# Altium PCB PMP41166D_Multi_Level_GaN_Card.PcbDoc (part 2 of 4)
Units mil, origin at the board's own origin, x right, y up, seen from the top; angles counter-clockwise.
Board outline 3221.72 x 1840 mil, 6 copper layers (Top Layer, Signal Layer 1, Signal Layer 2, Signal Layer 3, Signal Layer 4, Bottom Layer), stack 51.8 mil thick; 155 components, 123 nets, 580 pads, 278 vias.
Unrouted connection lines stored in the file: 2.
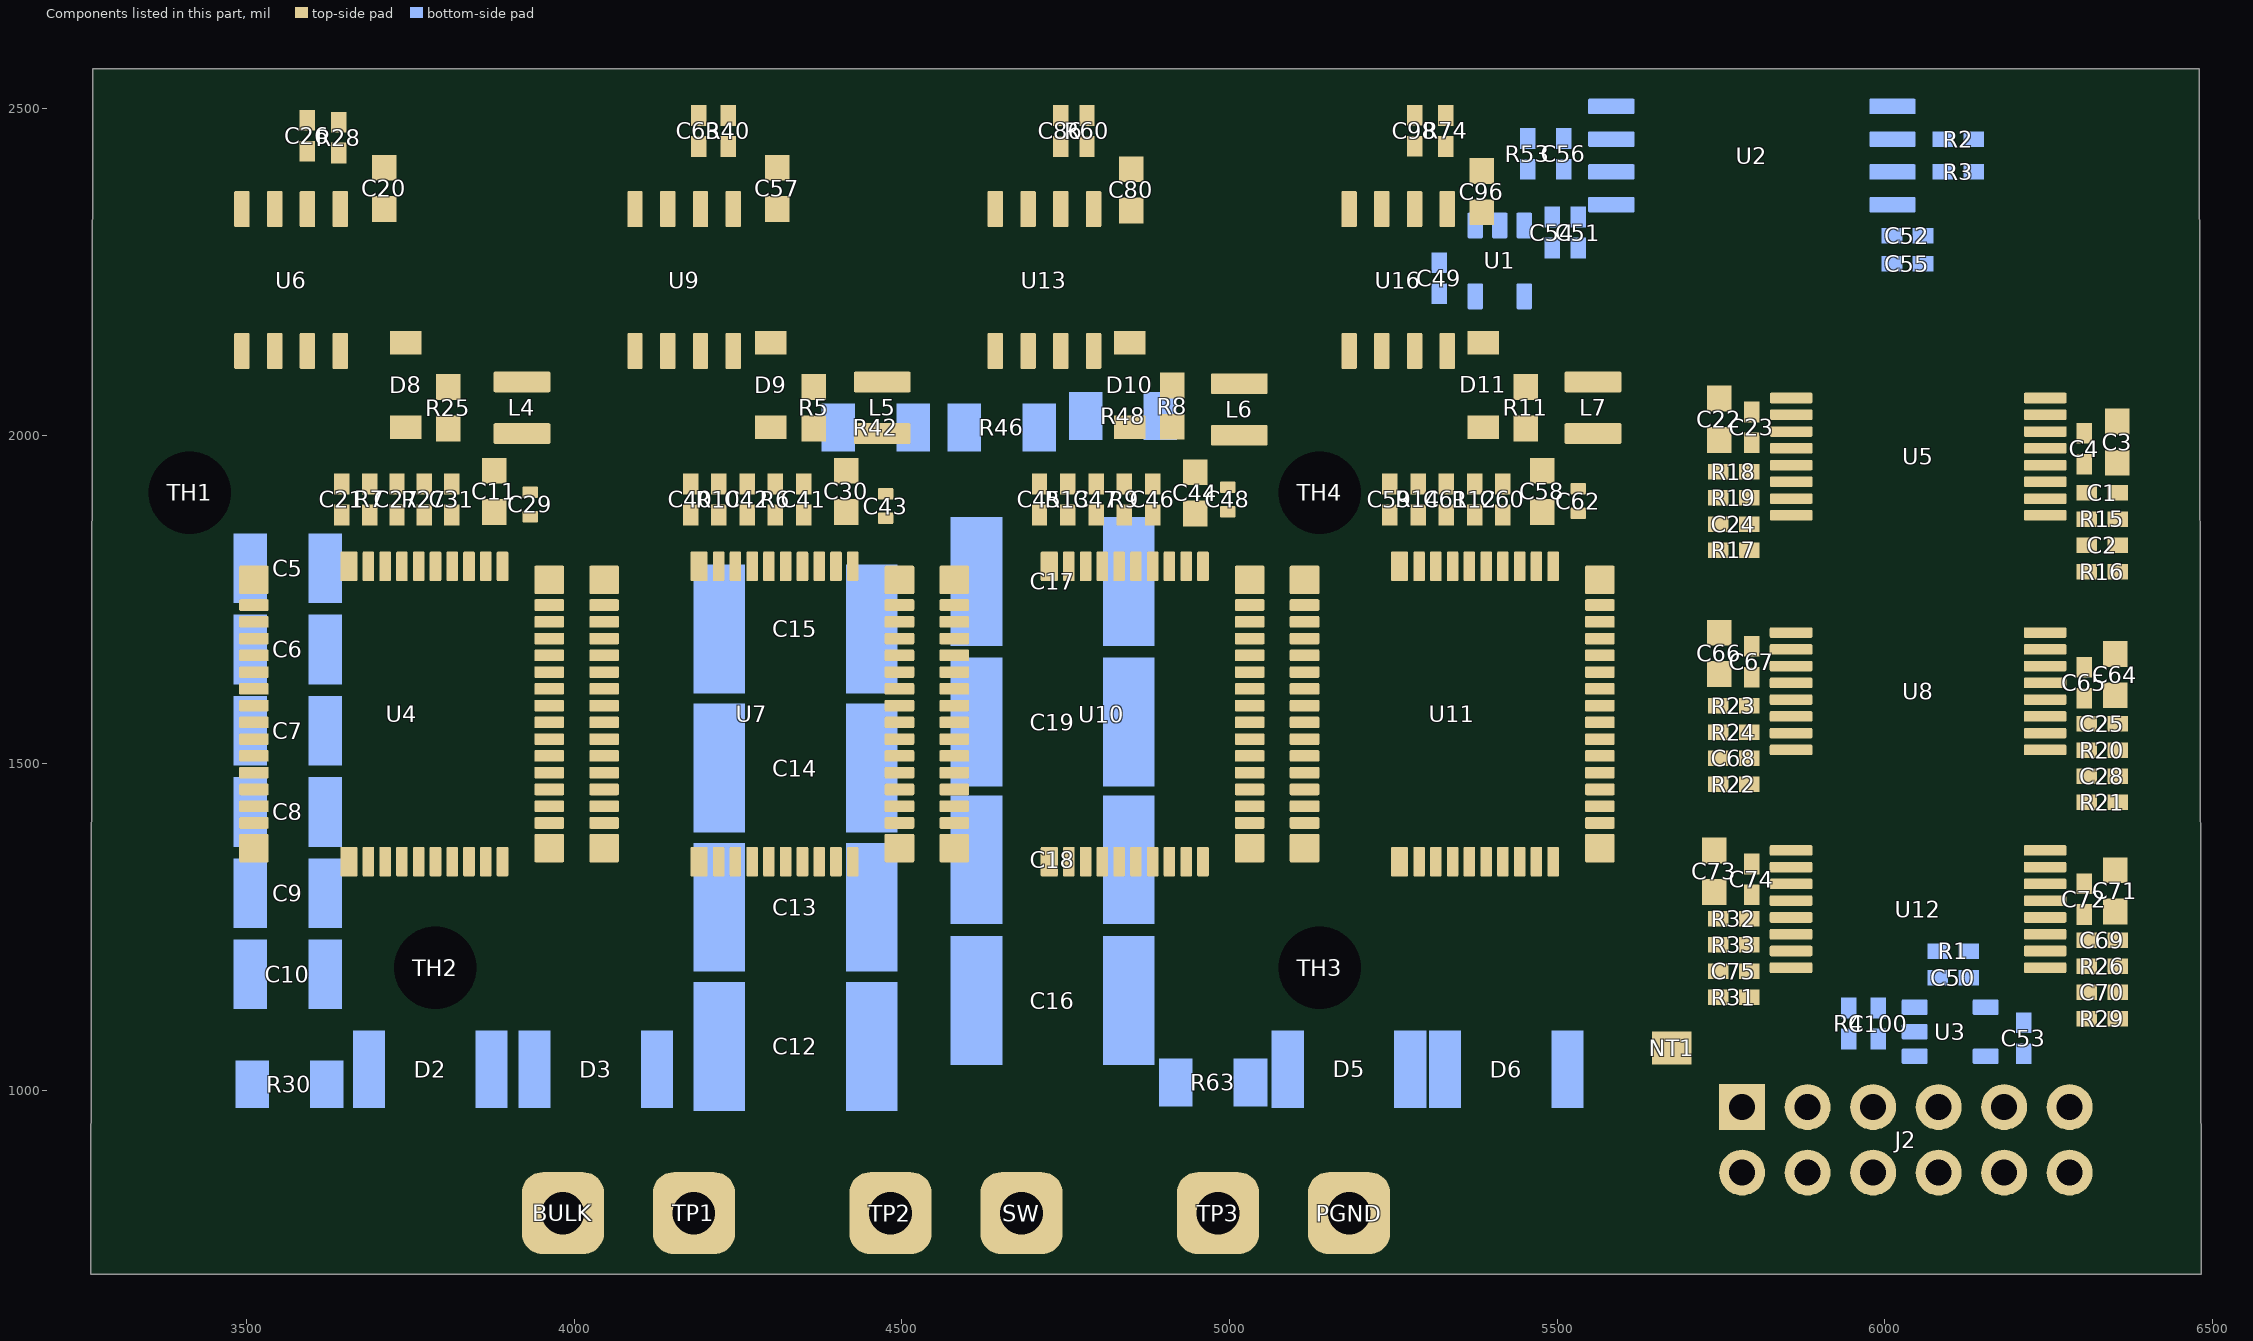
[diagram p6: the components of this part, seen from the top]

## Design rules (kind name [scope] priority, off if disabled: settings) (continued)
PolygonConnect PolygonConnect_38 [All vs IsNamedPolygon('SWNODE') Or  IsNamedPolygon('D403_2') Or  IsNamedPolygon('D403_2') Or  IsNamedPolygon('PGND') Or  IsNamedPolygon('BOTTOM_LAYER_NETC106_2_P030') Or  IsNamedPolygon('C102_1') Or  IsNamedPolygon('SGND') Or  IsNamedPolygon('TOP_LAYER_54V1_P046') Or  IsNamedPolygon('TOP_LAYER_54V2_P048') Or  IsNamedPolygon('TOP_LAYER_54V2_P048') Or  IsNamedPolygon('C108_1') Or  IsNamedPolygon('C108_1') Or  IsNamedPolygon('C108_1') Or  IsNamedPolygon('C108_1') Or  IsNamedPolygon('C108_1') Or  IsNamedPolygon('C108_1') Or  IsNamedPolygon('PGND') Or  IsNamedPolygon('ZCD') Or  IsNamedPolygon('Line') Or  IsNamedPolygon('5Vp') Or  IsNamedPolygon('12Vp') Or  IsNamedPolygon('T200_4') Or  IsNamedPolygon('T200_6') Or  IsNamedPolygon('SWNODE3') Or  IsNamedPolygon('T200_4') Or  IsNamedPolygon('T200_6') Or  IsNamedPolygon('SWNODE4') Or  IsNamedPolygon('VSR') Or  IsNamedPolygon('Iout_SNS') Or  IsNamedPolygon('SIGNAL_LAYER_2_VBB_P094') Or  IsNamedPolygon('Vbulk1') Or  IsNamedPolygon('VBB') Or  IsNamedPolygon('SIGNAL_LAYER_1_VBULK1_P106') Or  IsNamedPolygon('Line') Or  IsNamedPolygon('Line') Or  IsNamedPolygon('Line') Or  IsNamedPolygon('D404_2') Or  IsNamedPolygon('VBB') Or  IsNamedPolygon('D400_2') Or  IsNamedPolygon('SGND') Or  IsNamedPolygon('PGND') Or  IsNamedPolygon('TOP_LAYER_12VS_P126') Or  IsNamedPolygon('BOTTOM_LAYER_54V1_P128') Or  IsNamedPolygon('LEG3_HS_DRV') Or  IsNamedPolygon('LEG4_LS_DRV') Or  IsNamedPolygon('LEG4_HS_DRV') Or  IsNamedPolygon('SWNODE4') Or  IsNamedPolygon('SWNODE3') Or  IsNamedPolygon('T200_6') Or  IsNamedPolygon('T200_4') Or  IsNamedPolygon('VBB') Or  IsNamedPolygon('5Vs') Or  IsNamedPolygon('SGND') Or  IsNamedPolygon('Iout_SNS') Or  IsNamedPolygon('SGND') Or  IsNamedPolygon('SWNODE3') Or  IsNamedPolygon('SWNODE3') Or  IsNamedPolygon('SWNODE3') Or  IsNamedPolygon('SWNODE3') Or  IsNamedPolygon('SGND') Or  IsNamedPolygon('SGND') Or  IsNamedPolygon('SGND') Or  IsNamedPolygon('SWNODE4') Or  IsNamedPolygon('SWNODE4') Or  IsNamedPolygon('SWNODE4') Or  IsNamedPolygon('VSR') Or  IsNamedPolygon('SWNODE3') Or  IsNamedPolygon('SGND') Or  IsNamedPolygon('SGND') Or  IsNamedPolygon('SGND') Or  IsNamedPolygon('SGND') Or  IsNamedPolygon('SGND') Or  IsNamedPolygon('SGND') Or  IsNamedPolygon('BOTTOM_LAYER_54V1_P128') Or  IsNamedPolygon('SGND') Or  IsNamedPolygon('VSR') Or  IsNamedPolygon('C102_1') Or  IsNamedPolygon('C102_1') Or  IsNamedPolygon('C102_1') Or  IsNamedPolygon('C102_1') Or  IsNamedPolygon('C102_1') Or  IsNamedPolygon('ZCD') Or  IsNamedPolygon('PGND') Or  IsNamedPolygon('PGND') Or  IsNamedPolygon('Vbulk1') Or  IsNamedPolygon('VBB') Or  IsNamedPolygon('Vbulk1') Or  IsNamedPolygon('Vbulk1') Or  IsNamedPolygon('ZCD') Or  IsNamedPolygon('Neutral') Or  IsNamedPolygon('Neutral')] p22: connectstyle=Direct reliefconductorwidth=10 reliefentries=4 polygonreliefangle="90 Angle" airgapwidth=10
PolygonConnect PolygonConnect_37 [All vs IsNamedPolygon('SGND') Or  IsNamedPolygon('SWNODE4') Or  IsNamedPolygon('5Vp') Or  IsNamedPolygon('SWNODE4') Or  IsNamedPolygon('VBB') Or  IsNamedPolygon('Line') Or  IsNamedPolygon('SGND') Or  IsNamedPolygon('SIGNAL_LAYER_2_C102_1_P032') Or  IsNamedPolygon('TOP_LAYER_54V2_P048') Or  IsNamedPolygon('ZCD') Or  IsNamedPolygon('PGND') Or  IsNamedPolygon('SIGNAL_LAYER_2_VBB_P094') Or  IsNamedPolygon('Line') Or  IsNamedPolygon('Line') Or  IsNamedPolygon('D404_2') Or  IsNamedPolygon('PGND') Or  IsNamedPolygon('SIGNAL_LAYER_1_ZCD_P108') Or  IsNamedPolygon('SWNODE3') Or  IsNamedPolygon('SIGNAL_LAYER_4_C102_1_P038') Or  IsNamedPolygon('SWNODE3') Or  IsNamedPolygon('LEG4_HS_DRV') Or  IsNamedPolygon('SWNODE4') Or  IsNamedPolygon('5Vs') Or  IsNamedPolygon('VBB') Or  IsNamedPolygon('TOP_LAYER_54V2_P048') Or  IsNamedPolygon('C102_1') Or  IsNamedPolygon('LEG4_LS_DRV') Or  IsNamedPolygon('T200_4') Or  IsNamedPolygon('SWNODE3') Or  IsNamedPolygon('Line') Or  IsNamedPolygon('SGND') Or  IsNamedPolygon('SGND') Or  IsNamedPolygon('SWNODE4') Or  IsNamedPolygon('12Vp') Or  IsNamedPolygon('BOTTOM_LAYER_NETC106_2_P030') Or  IsNamedPolygon('T200_4') Or  IsNamedPolygon('Vbulk1') Or  IsNamedPolygon('C108_1') Or  IsNamedPolygon('BOTTOM_LAYER_54V1_P128') Or  IsNamedPolygon('BOTTOM_LAYER_54V1_P128') Or  IsNamedPolygon('SWNODE') Or  IsNamedPolygon('Iout_SNS') Or  IsNamedPolygon('VSR') Or  IsNamedPolygon('D400_2') Or  IsNamedPolygon('D403_2') Or  IsNamedPolygon('SWNODE3') Or  IsNamedPolygon('T200_6') Or  IsNamedPolygon('SWNODE3') Or  IsNamedPolygon('C108_1') Or  IsNamedPolygon('PGND') Or  IsNamedPolygon('BOTTOM_LAYER_VBULK1_P096') Or  IsNamedPolygon('BOTTOM_LAYER_54V1_P128') Or  IsNamedPolygon('TOP_LAYER_12VS_P126') Or  IsNamedPolygon('SIGNAL_LAYER_1_VBULK1_P106') Or  IsNamedPolygon('T200_4') Or  IsNamedPolygon('SGND') Or  IsNamedPolygon('C108_1') Or  IsNamedPolygon('SWNODE3') Or  IsNamedPolygon('T200_6') Or  IsNamedPolygon('T200_6') Or  IsNamedPolygon('T200_6') Or  IsNamedPolygon('SGND') Or  IsNamedPolygon('C108_1') Or  IsNamedPolygon('SGND') Or  IsNamedPolygon('VBB') Or  IsNamedPolygon('T200_4') Or  IsNamedPolygon('LEG3_HS_DRV') Or  IsNamedPolygon('C108_1') Or  IsNamedPolygon('D403_2') Or  IsNamedPolygon('Iout_SNS') Or  IsNamedPolygon('C108_1') Or  IsNamedPolygon('SWNODE4')] p23: connectstyle=Direct reliefconductorwidth=10 reliefentries=4 polygonreliefangle="90 Angle" airgapwidth=10
PolygonConnect PolygonConnect_36 [All vs IsNamedPolygon('PGND') Or  IsNamedPolygon('BOTTOM_LAYER_54V1_P128') Or  IsNamedPolygon('SGND') Or  IsNamedPolygon('LEG4_LS_DRV') Or  IsNamedPolygon('TOP_LAYER_12VS_P126') Or  IsNamedPolygon('LEG4_HS_DRV') Or  IsNamedPolygon('LEG3_HS_DRV') Or  IsNamedPolygon('SGND') Or  IsNamedPolygon('C108_1') Or  IsNamedPolygon('12Vp') Or  IsNamedPolygon('D403_2') Or  IsNamedPolygon('SIGNAL_LAYER_1_ZCD_P108') Or  IsNamedPolygon('C108_1') Or  IsNamedPolygon('BOTTOM_LAYER_VBULK1_P096') Or  IsNamedPolygon('SWNODE') Or  IsNamedPolygon('T200_4') Or  IsNamedPolygon('D400_2') Or  IsNamedPolygon('C102_1') Or  IsNamedPolygon('Line') Or  IsNamedPolygon('VBB') Or  IsNamedPolygon('Line') Or  IsNamedPolygon('TOP_LAYER_54V2_P048') Or  IsNamedPolygon('BOTTOM_LAYER_NETC106_2_P030') Or  IsNamedPolygon('SIGNAL_LAYER_1_VBULK1_P106') Or  IsNamedPolygon('Line') Or  IsNamedPolygon('5Vp') Or  IsNamedPolygon('BOTTOM_LAYER_54V1_P128') Or  IsNamedPolygon('D404_2') Or  IsNamedPolygon('C108_1') Or  IsNamedPolygon('VSR') Or  IsNamedPolygon('T200_6') Or  IsNamedPolygon('VBB') Or  IsNamedPolygon('C108_1') Or  IsNamedPolygon('SIGNAL_LAYER_2_C102_1_P032') Or  IsNamedPolygon('SGND') Or  IsNamedPolygon('PGND') Or  IsNamedPolygon('SIGNAL_LAYER_4_C102_1_P038') Or  IsNamedPolygon('Vbulk1') Or  IsNamedPolygon('TOP_LAYER_54V2_P048') Or  IsNamedPolygon('Iout_SNS') Or  IsNamedPolygon('PGND') Or  IsNamedPolygon('T200_4') Or  IsNamedPolygon('ZCD') Or  IsNamedPolygon('Line') Or  IsNamedPolygon('C108_1') Or  IsNamedPolygon('D403_2') Or  IsNamedPolygon('SIGNAL_LAYER_2_VBB_P094') Or  IsNamedPolygon('SGND') Or  IsNamedPolygon('C108_1') Or  IsNamedPolygon('SIGNAL_LAYER_1_IOUT_SNS_P044') Or  IsNamedPolygon('BOTTOM_LAYER_54V1_P128') Or  IsNamedPolygon('T200_6')] p24: connectstyle=Direct reliefconductorwidth=10 reliefentries=4 polygonreliefangle="90 Angle" airgapwidth=10
PolygonConnect PolygonConnect_35 [All vs IsNamedPolygon('SWNODE') Or  IsNamedPolygon('D403_2') Or  IsNamedPolygon('D403_2') Or  IsNamedPolygon('PGND') Or  IsNamedPolygon('BOTTOM_LAYER_NETC106_2_P030') Or  IsNamedPolygon('SIGNAL_LAYER_2_C102_1_P032') Or  IsNamedPolygon('C102_1') Or  IsNamedPolygon('SIGNAL_LAYER_4_C102_1_P038') Or  IsNamedPolygon('SGND') Or  IsNamedPolygon('SIGNAL_LAYER_1_IOUT_SNS_P044') Or  IsNamedPolygon('BOTTOM_LAYER_54V1_P128') Or  IsNamedPolygon('TOP_LAYER_54V2_P048') Or  IsNamedPolygon('BOTTOM_LAYER_54V1_P128') Or  IsNamedPolygon('TOP_LAYER_54V2_P048') Or  IsNamedPolygon('C108_1') Or  IsNamedPolygon('C108_1') Or  IsNamedPolygon('C108_1') Or  IsNamedPolygon('C108_1') Or  IsNamedPolygon('C108_1') Or  IsNamedPolygon('C108_1') Or  IsNamedPolygon('PGND') Or  IsNamedPolygon('ZCD') Or  IsNamedPolygon('Line') Or  IsNamedPolygon('5Vp') Or  IsNamedPolygon('12Vp') Or  IsNamedPolygon('T200_4') Or  IsNamedPolygon('T200_6') Or  IsNamedPolygon('SGND') Or  IsNamedPolygon('T200_4') Or  IsNamedPolygon('T200_6') Or  IsNamedPolygon('SGND') Or  IsNamedPolygon('VSR') Or  IsNamedPolygon('Iout_SNS') Or  IsNamedPolygon('SIGNAL_LAYER_2_VBB_P094') Or  IsNamedPolygon('BOTTOM_LAYER_VBULK1_P096') Or  IsNamedPolygon('Vbulk1') Or  IsNamedPolygon('VBB') Or  IsNamedPolygon('SIGNAL_LAYER_1_VBULK1_P106') Or  IsNamedPolygon('SIGNAL_LAYER_1_ZCD_P108') Or  IsNamedPolygon('Line') Or  IsNamedPolygon('Line') Or  IsNamedPolygon('Line') Or  IsNamedPolygon('D404_2') Or  IsNamedPolygon('VBB') Or  IsNamedPolygon('D400_2') Or  IsNamedPolygon('SGND') Or  IsNamedPolygon('PGND') Or  IsNamedPolygon('TOP_LAYER_12VS_P126') Or  IsNamedPolygon('BOTTOM_LAYER_54V1_P128') Or  IsNamedPolygon('LEG3_HS_DRV')] p25: connectstyle=Direct reliefconductorwidth=10 reliefentries=4 polygonreliefangle="90 Angle" airgapwidth=10
PolygonConnect PolygonConnect_34 [All vs IsNamedPolygon('SWNODE') Or  IsNamedPolygon('D403_2') Or  IsNamedPolygon('D403_2') Or  IsNamedPolygon('PGND') Or  IsNamedPolygon('BOTTOM_LAYER_NETC106_2_P030') Or  IsNamedPolygon('SIGNAL_LAYER_2_C102_1_P032') Or  IsNamedPolygon('C102_1') Or  IsNamedPolygon('SIGNAL_LAYER_4_C102_1_P038') Or  IsNamedPolygon('SGND') Or  IsNamedPolygon('SIGNAL_LAYER_1_IOUT_SNS_P044') Or  IsNamedPolygon('BOTTOM_LAYER_54V1_P128') Or  IsNamedPolygon('TOP_LAYER_54V2_P048') Or  IsNamedPolygon('BOTTOM_LAYER_54V1_P128') Or  IsNamedPolygon('TOP_LAYER_54V2_P048') Or  IsNamedPolygon('C108_1') Or  IsNamedPolygon('C108_1') Or  IsNamedPolygon('C108_1') Or  IsNamedPolygon('C108_1') Or  IsNamedPolygon('C108_1') Or  IsNamedPolygon('C108_1') Or  IsNamedPolygon('PGND') Or  IsNamedPolygon('ZCD') Or  IsNamedPolygon('Line') Or  IsNamedPolygon('5Vp') Or  IsNamedPolygon('12Vp') Or  IsNamedPolygon('T200_4') Or  IsNamedPolygon('T200_6') Or  IsNamedPolygon('SGND') Or  IsNamedPolygon('T200_4') Or  IsNamedPolygon('T200_6') Or  IsNamedPolygon('SGND') Or  IsNamedPolygon('VSR') Or  IsNamedPolygon('Iout_SNS') Or  IsNamedPolygon('SIGNAL_LAYER_2_VBB_P094') Or  IsNamedPolygon('BOTTOM_LAYER_VBULK1_P096') Or  IsNamedPolygon('Vbulk1') Or  IsNamedPolygon('VBB') Or  IsNamedPolygon('SIGNAL_LAYER_1_VBULK1_P106') Or  IsNamedPolygon('SIGNAL_LAYER_1_ZCD_P108') Or  IsNamedPolygon('Line') Or  IsNamedPolygon('Line') Or  IsNamedPolygon('Line') Or  IsNamedPolygon('D404_2') Or  IsNamedPolygon('VBB') Or  IsNamedPolygon('D400_2') Or  IsNamedPolygon('SGND')] p26: connectstyle=Direct reliefconductorwidth=10 reliefentries=4 polygonreliefangle="90 Angle" airgapwidth=10
PolygonConnect PolygonConnect_33 [All vs IsNamedPolygon('SIGNAL_LAYER_1_VBULK1_P106')] p27: connectstyle=Direct reliefconductorwidth=10 reliefentries=4 polygonreliefangle="90 Angle" airgapwidth=10
PolygonConnect PolygonConnect_32 [All vs IsNamedPolygon('SIGNAL_LAYER_1_VBULK1_P106')] p28: connectstyle=Direct reliefconductorwidth=10 reliefentries=4 polygonreliefangle="90 Angle" airgapwidth=10
PolygonConnect PolygonConnect_31 [All vs IsNamedPolygon('SIGNAL_LAYER_1_VBULK1_P106')] p29: connectstyle=Direct reliefconductorwidth=10 reliefentries=4 polygonreliefangle="90 Angle" airgapwidth=10
PolygonConnect PolygonConnect_30 [All vs IsNamedPolygon('VBB')] p30: connectstyle=Direct reliefconductorwidth=10 reliefentries=4 polygonreliefangle="90 Angle" airgapwidth=10
PolygonConnect PolygonConnect_29 [All vs IsNamedPolygon('SGND')] p31: connectstyle=Direct reliefconductorwidth=10 reliefentries=4 polygonreliefangle="90 Angle" airgapwidth=10
PolygonConnect PolygonConnect_28 [All vs IsNamedPolygon('Vbulk1')] p32: connectstyle=Direct reliefconductorwidth=10 reliefentries=4 polygonreliefangle="90 Angle" airgapwidth=10
PolygonConnect PolygonConnect_27 [All vs IsNamedPolygon('BOTTOM_LAYER_VBULK1_P096')] p33: connectstyle=Direct reliefconductorwidth=10 reliefentries=4 polygonreliefangle="90 Angle" airgapwidth=10
PolygonConnect PolygonConnect_26 [All vs IsNamedPolygon('SIGNAL_LAYER_2_VBB_P094')] p34: connectstyle=Direct reliefconductorwidth=10 reliefentries=4 polygonreliefangle="90 Angle" airgapwidth=10
PolygonConnect PolygonConnect_25 [All vs IsNamedPolygon('C108_1')] p35: connectstyle=Direct reliefconductorwidth=10 reliefentries=4 polygonreliefangle="90 Angle" airgapwidth=10
PolygonConnect PolygonConnect_24 [All vs IsNamedPolygon('BOTTOM_LAYER_EARTH_P100')] p36: connectstyle=Direct reliefconductorwidth=10 reliefentries=4 polygonreliefangle="90 Angle" airgapwidth=10
PolygonConnect PolygonConnect_23 [All vs IsNamedPolygon('BOTTOM_LAYER_54V1_P128')] p37: connectstyle=Direct reliefconductorwidth=10 reliefentries=4 polygonreliefangle="90 Angle" airgapwidth=10
PolygonConnect PolygonConnect_22 [All vs IsNamedPolygon('BOTTOM_LAYER_VBULK1_P096')] p38: connectstyle=Direct reliefconductorwidth=10 reliefentries=4 polygonreliefangle="90 Angle" airgapwidth=10
PolygonConnect PolygonConnect_21 [All vs IsNamedPolygon('SIGNAL_LAYER_2_VBB_P094')] p39: connectstyle=Direct reliefconductorwidth=10 reliefentries=4 polygonreliefangle="90 Angle" airgapwidth=10
PolygonConnect PolygonConnect_20 [All vs IsNamedPolygon('Iout_SNS')] p40: connectstyle=Direct reliefconductorwidth=10 reliefentries=4 polygonreliefangle="90 Angle" airgapwidth=10
PolygonConnect PolygonConnect_19 [All vs IsNamedPolygon('C108_1') Or  IsNamedPolygon('BOTTOM_LAYER_NETC106_2_P030') Or  IsNamedPolygon('D403_2') Or  IsNamedPolygon('C102_1') Or  IsNamedPolygon('SWNODE') Or  IsNamedPolygon('D403_2') Or  IsNamedPolygon('SIGNAL_LAYER_4_C102_1_P038') Or  IsNamedPolygon('PGND') Or  IsNamedPolygon('SIGNAL_LAYER_2_C102_1_P032') Or  IsNamedPolygon('SIGNAL_LAYER_1_IOUT_SNS_P044') Or  IsNamedPolygon('SGND') Or  IsNamedPolygon('C108_1') Or  IsNamedPolygon('BOTTOM_LAYER_54V1_P128') Or  IsNamedPolygon('C108_1') Or  IsNamedPolygon('C108_1') Or  IsNamedPolygon('TOP_LAYER_54V2_P048') Or  IsNamedPolygon('BOTTOM_LAYER_54V1_P128') Or  IsNamedPolygon('TOP_LAYER_54V2_P048') Or  IsNamedPolygon('C108_1') Or  IsNamedPolygon('C108_1') Or  IsNamedPolygon('12Vp') Or  IsNamedPolygon('5Vp') Or  IsNamedPolygon('Line') Or  IsNamedPolygon('T200_4') Or  IsNamedPolygon('SGND') Or  IsNamedPolygon('VSR') Or  IsNamedPolygon('ZCD') Or  IsNamedPolygon('PGND') Or  IsNamedPolygon('T200_6') Or  IsNamedPolygon('Neutral') Or  IsNamedPolygon('T200_4') Or  IsNamedPolygon('SGND') Or  IsNamedPolygon('T200_6')] p41: connectstyle=Direct reliefconductorwidth=10 reliefentries=4 polygonreliefangle="90 Angle" airgapwidth=10
PolygonConnect PolygonConnect_18 [All vs IsNamedPolygon('SWNODE') Or  IsNamedPolygon('D403_2') Or  IsNamedPolygon('D403_2') Or  IsNamedPolygon('PGND') Or  IsNamedPolygon('BOTTOM_LAYER_NETC106_2_P030') Or  IsNamedPolygon('SIGNAL_LAYER_2_C102_1_P032') Or  IsNamedPolygon('C102_1') Or  IsNamedPolygon('SIGNAL_LAYER_4_C102_1_P038') Or  IsNamedPolygon('SGND') Or  IsNamedPolygon('SIGNAL_LAYER_1_IOUT_SNS_P044') Or  IsNamedPolygon('BOTTOM_LAYER_54V1_P128') Or  IsNamedPolygon('TOP_LAYER_54V2_P048') Or  IsNamedPolygon('BOTTOM_LAYER_54V1_P128') Or  IsNamedPolygon('TOP_LAYER_54V2_P048') Or  IsNamedPolygon('C108_1') Or  IsNamedPolygon('C108_1') Or  IsNamedPolygon('C108_1') Or  IsNamedPolygon('C108_1') Or  IsNamedPolygon('C108_1') Or  IsNamedPolygon('C108_1') Or  IsNamedPolygon('Neutral') Or  IsNamedPolygon('PGND') Or  IsNamedPolygon('ZCD') Or  IsNamedPolygon('Line') Or  IsNamedPolygon('5Vp') Or  IsNamedPolygon('12Vp') Or  IsNamedPolygon('T200_4') Or  IsNamedPolygon('T200_6') Or  IsNamedPolygon('SGND') Or  IsNamedPolygon('T200_4') Or  IsNamedPolygon('T200_6') Or  IsNamedPolygon('SGND')] p42: connectstyle=Direct reliefconductorwidth=10 reliefentries=4 polygonreliefangle="90 Angle" airgapwidth=10
PolygonConnect PolygonConnect_17 [All vs IsNamedPolygon('12Vp') Or  IsNamedPolygon('T200_4') Or  IsNamedPolygon('T200_6') Or  IsNamedPolygon('SGND') Or  IsNamedPolygon('TOP_LAYER_54V2_P048') Or  IsNamedPolygon('SIGNAL_LAYER_1_IOUT_SNS_P044') Or  IsNamedPolygon('BOTTOM_LAYER_54V1_P128') Or  IsNamedPolygon('SGND') Or  IsNamedPolygon('C102_1') Or  IsNamedPolygon('SIGNAL_LAYER_4_C102_1_P038') Or  IsNamedPolygon('Neutral') Or  IsNamedPolygon('C108_1') Or  IsNamedPolygon('C108_1') Or  IsNamedPolygon('C108_1') Or  IsNamedPolygon('BOTTOM_LAYER_54V1_P128') Or  IsNamedPolygon('TOP_LAYER_54V2_P048') Or  IsNamedPolygon('SIGNAL_LAYER_2_C102_1_P032') Or  IsNamedPolygon('SWNODE') Or  IsNamedPolygon('C108_1') Or  IsNamedPolygon('C108_1') Or  IsNamedPolygon('C108_1') Or  IsNamedPolygon('D403_2') Or  IsNamedPolygon('BOTTOM_LAYER_NETC106_2_P030') Or  IsNamedPolygon('PGND') Or  IsNamedPolygon('D403_2') Or  IsNamedPolygon('5Vp') Or  IsNamedPolygon('PGND') Or  IsNamedPolygon('ZCD') Or  IsNamedPolygon('Line')] p43: connectstyle=Direct reliefconductorwidth=10 reliefentries=4 polygonreliefangle="90 Angle" airgapwidth=10
PolygonConnect PolygonConnect_16 [All vs IsNamedPolygon('D403_2') Or  IsNamedPolygon('C102_1') Or  IsNamedPolygon('C108_1') Or  IsNamedPolygon('SWNODE') Or  IsNamedPolygon('BOTTOM_LAYER_54V1_P128') Or  IsNamedPolygon('SGND') Or  IsNamedPolygon('Line') Or  IsNamedPolygon('ZCD') Or  IsNamedPolygon('SIGNAL_LAYER_1_IOUT_SNS_P044') Or  IsNamedPolygon('Neutral') Or  IsNamedPolygon('PGND') Or  IsNamedPolygon('12Vp') Or  IsNamedPolygon('C108_1') Or  IsNamedPolygon('C108_1') Or  IsNamedPolygon('TOP_LAYER_54V2_P048') Or  IsNamedPolygon('C108_1') Or  IsNamedPolygon('TOP_LAYER_54V2_P048') Or  IsNamedPolygon('T200_4') Or  IsNamedPolygon('T200_6') Or  IsNamedPolygon('D403_2') Or  IsNamedPolygon('C108_1') Or  IsNamedPolygon('C108_1') Or  IsNamedPolygon('SIGNAL_LAYER_4_C102_1_P038') Or  IsNamedPolygon('SIGNAL_LAYER_2_C102_1_P032') Or  IsNamedPolygon('PGND') Or  IsNamedPolygon('BOTTOM_LAYER_NETC106_2_P030') Or  IsNamedPolygon('5Vp') Or  IsNamedPolygon('BOTTOM_LAYER_54V1_P128')] p44: connectstyle=Direct reliefconductorwidth=10 reliefentries=4 polygonreliefangle="90 Angle" airgapwidth=10
PolygonConnect PolygonConnect_15 [All vs IsNamedPolygon('SWNODE') Or  IsNamedPolygon('D403_2') Or  IsNamedPolygon('D403_2') Or  IsNamedPolygon('SIGNAL_LAYER_1_PGND_P018') Or  IsNamedPolygon('PGND') Or  IsNamedPolygon('BOTTOM_LAYER_NETC106_2_P030') Or  IsNamedPolygon('SIGNAL_LAYER_2_C102_1_P032') Or  IsNamedPolygon('C102_1') Or  IsNamedPolygon('SIGNAL_LAYER_4_C102_1_P038') Or  IsNamedPolygon('SGND') Or  IsNamedPolygon('SIGNAL_LAYER_1_IOUT_SNS_P044') Or  IsNamedPolygon('BOTTOM_LAYER_54V1_P128') Or  IsNamedPolygon('TOP_LAYER_54V2_P048') Or  IsNamedPolygon('BOTTOM_LAYER_54V1_P128') Or  IsNamedPolygon('TOP_LAYER_54V2_P048') Or  IsNamedPolygon('C108_1') Or  IsNamedPolygon('C108_1') Or  IsNamedPolygon('C108_1') Or  IsNamedPolygon('C108_1') Or  IsNamedPolygon('C108_1') Or  IsNamedPolygon('C108_1') Or  IsNamedPolygon('Neutral') Or  IsNamedPolygon('PGND') Or  IsNamedPolygon('ZCD') Or  IsNamedPolygon('Line') Or  IsNamedPolygon('5Vp') Or  IsNamedPolygon('12Vp')] p45: connectstyle=Direct reliefconductorwidth=10 reliefentries=4 polygonreliefangle="90 Angle" airgapwidth=10
PolygonConnect PolygonConnect_14 [All vs IsNamedPolygon('TOP_LAYER_54V2_P048') Or  IsNamedPolygon('C108_1') Or  IsNamedPolygon('C108_1') Or  IsNamedPolygon('SIGNAL_LAYER_4_C102_1_P038') Or  IsNamedPolygon('C102_1') Or  IsNamedPolygon('SIGNAL_LAYER_2_C102_1_P032') Or  IsNamedPolygon('SIGNAL_LAYER_1_PGND_P018') Or  IsNamedPolygon('SIGNAL_LAYER_1_IOUT_SNS_P044') Or  IsNamedPolygon('SGND') Or  IsNamedPolygon('C108_1') Or  IsNamedPolygon('ZCD') Or  IsNamedPolygon('PGND') Or  IsNamedPolygon('TOP_LAYER_54V2_P048') Or  IsNamedPolygon('BOTTOM_LAYER_NETC106_2_P030') Or  IsNamedPolygon('PGND') Or  IsNamedPolygon('C108_1') Or  IsNamedPolygon('C108_1') Or  IsNamedPolygon('D403_2') Or  IsNamedPolygon('Line') Or  IsNamedPolygon('C108_1') Or  IsNamedPolygon('Neutral') Or  IsNamedPolygon('SWNODE') Or  IsNamedPolygon('D403_2') Or  IsNamedPolygon('BOTTOM_LAYER_54V1_P128') Or  IsNamedPolygon('BOTTOM_LAYER_54V1_P128')] p46: connectstyle=Direct reliefconductorwidth=10 reliefentries=4 polygonreliefangle="90 Angle" airgapwidth=10
PolygonConnect PolygonConnect_13 [All vs IsNamedPolygon('PGND') Or  IsNamedPolygon('D403_2') Or  IsNamedPolygon('SIGNAL_LAYER_1_PGND_P018') Or  IsNamedPolygon('D403_2') Or  IsNamedPolygon('SWNODE') Or  IsNamedPolygon('SGND') Or  IsNamedPolygon('BOTTOM_LAYER_54V1_P128') Or  IsNamedPolygon('C108_1') Or  IsNamedPolygon('SIGNAL_LAYER_4_C102_1_P038') Or  IsNamedPolygon('C108_1') Or  IsNamedPolygon('TOP_LAYER_54V2_P048') Or  IsNamedPolygon('TOP_LAYER_54V2_P048') Or  IsNamedPolygon('C108_1') Or  IsNamedPolygon('C108_1') Or  IsNamedPolygon('C108_1') Or  IsNamedPolygon('BOTTOM_LAYER_NETC106_2_P030') Or  IsNamedPolygon('SIGNAL_LAYER_1_IOUT_SNS_P044') Or  IsNamedPolygon('C108_1') Or  IsNamedPolygon('C102_1') Or  IsNamedPolygon('SIGNAL_LAYER_2_C102_1_P032') Or  IsNamedPolygon('BOTTOM_LAYER_54V1_P128')] p47: connectstyle=Direct reliefconductorwidth=10 reliefentries=4 polygonreliefangle="90 Angle" airgapwidth=10
PolygonConnect PolygonConnect_12 [All vs IsNamedPolygon('TOP_LAYER_54V2_P048')] p48: connectstyle=Direct reliefconductorwidth=10 reliefentries=4 polygonreliefangle="90 Angle" airgapwidth=10
PolygonConnect PolygonConnect_11 [All vs IsNamedPolygon('BOTTOM_LAYER_54V1_P128')] p49: connectstyle=Direct reliefconductorwidth=10 reliefentries=4 polygonreliefangle="90 Angle" airgapwidth=10
PolygonConnect PolygonConnect_10 [All vs IsNamedPolygon('SIGNAL_LAYER_1_IOUT_SNS_P044')] p50: thpad.connectstyle=Direct thpad.reliefconductorwidth=10 thpad.reliefentries=4 thpad.polygonreliefangle="90 Angle" thpad.airgapwidth=10 smdpad.connectstyle=Relief smdpad.reliefconductorwidth=10 smdpad.reliefentries=4 smdpad.polygonreliefangle="90 Angle" smdpad.airgapwidth=10 via.connectstyle=Direct via.reliefconductorwidth=10 via.reliefentries=4 via.polygonreliefangle="90 Angle" via.airgapwidth=10
PolygonConnect PolygonConnect_9 [All vs IsNamedPolygon('SGND')] p51: thpad.connectstyle=Direct thpad.reliefconductorwidth=10 thpad.reliefentries=4 thpad.polygonreliefangle="90 Angle" thpad.airgapwidth=10 smdpad.connectstyle=Relief smdpad.reliefconductorwidth=10 smdpad.reliefentries=4 smdpad.polygonreliefangle="90 Angle" smdpad.airgapwidth=10 via.connectstyle=Direct via.reliefconductorwidth=10 via.reliefentries=4 via.polygonreliefangle="90 Angle" via.airgapwidth=10
PolygonConnect PolygonConnect_8 [All vs IsNamedPolygon('SGND')] p52: thpad.connectstyle=Direct thpad.reliefconductorwidth=10 thpad.reliefentries=4 thpad.polygonreliefangle="90 Angle" thpad.airgapwidth=10 smdpad.connectstyle=Relief smdpad.reliefconductorwidth=10 smdpad.reliefentries=4 smdpad.polygonreliefangle="90 Angle" smdpad.airgapwidth=10 via.connectstyle=Direct via.reliefconductorwidth=10 via.reliefentries=4 via.polygonreliefangle="90 Angle" via.airgapwidth=10
PolygonConnect PolygonConnect_7 [All vs IsNamedPolygon('SGND')] p53: thpad.connectstyle=Relief thpad.reliefconductorwidth=0 thpad.reliefentries=4 thpad.polygonreliefangle="90 Angle" thpad.airgapwidth=0 smdpad.connectstyle=Relief smdpad.reliefconductorwidth=10 smdpad.reliefentries=4 smdpad.polygonreliefangle="90 Angle" smdpad.airgapwidth=10 via.connectstyle=Relief via.reliefconductorwidth=10 via.reliefentries=4 via.polygonreliefangle="90 Angle" via.airgapwidth=10
PolygonConnect PolygonConnect_6 [All vs IsNamedPolygon('SGND')] p54: thpad.connectstyle=Direct thpad.reliefconductorwidth=10 thpad.reliefentries=4 thpad.polygonreliefangle="90 Angle" thpad.airgapwidth=10 smdpad.connectstyle=Relief smdpad.reliefconductorwidth=10 smdpad.reliefentries=4 smdpad.polygonreliefangle="90 Angle" smdpad.airgapwidth=10 via.connectstyle=Relief via.reliefconductorwidth=10 via.reliefentries=4 via.polygonreliefangle="90 Angle" via.airgapwidth=10
PolygonConnect PolygonConnect_5 [All vs IsNamedPolygon('SGND')] p55: thpad.connectstyle=Direct thpad.reliefconductorwidth=10 thpad.reliefentries=4 thpad.polygonreliefangle="90 Angle" thpad.airgapwidth=10 smdpad.connectstyle=Relief smdpad.reliefconductorwidth=10 smdpad.reliefentries=4 smdpad.polygonreliefangle="90 Angle" smdpad.airgapwidth=10 via.connectstyle=Relief via.reliefconductorwidth=10 via.reliefentries=4 via.polygonreliefangle="90 Angle" via.airgapwidth=10
PolygonConnect PolygonConnect_4 [All vs IsNamedPolygon('SIGNAL_LAYER_1_PGND_P018') Or  IsNamedPolygon('SWNODE') Or  IsNamedPolygon('D403_2') Or  IsNamedPolygon('SIGNAL_LAYER_4_C102_1_P038') Or  IsNamedPolygon('D403_2') Or  IsNamedPolygon('BOTTOM_LAYER_NETC106_2_P030') Or  IsNamedPolygon('C102_1') Or  IsNamedPolygon('PGND') Or  IsNamedPolygon('SIGNAL_LAYER_2_C102_1_P032')] p56: connectstyle=Direct reliefconductorwidth=10 reliefentries=4 polygonreliefangle="90 Angle" airgapwidth=10
PolygonConnect PolygonConnect_3 [All vs IsNamedPolygon('SWNODE') Or  IsNamedPolygon('D403_2') Or  IsNamedPolygon('Neutral') Or  IsNamedPolygon('C106_2') Or  IsNamedPolygon('D403_2') Or  IsNamedPolygon('Neutral') Or  IsNamedPolygon('Neutral')] p57: connectstyle=Direct reliefconductorwidth=10 reliefentries=4 polygonreliefangle="90 Angle" airgapwidth=10
PolygonConnect PolygonConnect_2 [All vs IsNamedPolygon('Neutral') Or  IsNamedPolygon('Neutral') Or  IsNamedPolygon('C106_2') Or  IsNamedPolygon('SWNODE') Or  IsNamedPolygon('Neutral')] p58: connectstyle=Direct reliefconductorwidth=10 reliefentries=4 polygonreliefangle="90 Angle" airgapwidth=10
PolygonConnect PolygonConnect_1 [All vs IsNamedPolygon('Neutral') Or  IsNamedPolygon('Neutral')] p59: connectstyle=Direct reliefconductorwidth=10 reliefentries=4 polygonreliefangle="90 Angle" airgapwidth=10
PolygonConnect [All] p60: connectstyle=Direct reliefconductorwidth=10 reliefentries=4 polygonreliefangle="90 Angle" airgapwidth=10
RoutingVias ThermalPadVias [IsVia and InAnyComponent] p1: holewidth=7.87 width=19.68 viastyle="Through Hole" minholewidth=7.87 minwidth=19.68 maxholewidth=12.99 maxwidth=23.62
RoutingVias [All] p2: holewidth=16 width=34 viastyle="Through Hole" minholewidth=7.87 minwidth=20 maxholewidth=40 maxwidth=65
SilkToBoardRegionClearance [Not ((IsComment or IsDesignator) And (Hide <> 'False')) and not InRegion(1000,500,4000,800)] p1:
SilkToSilkClearance SilkToSilkClearance_Pb-FreeLogo [(HasFootprint('Pb-Free_Overlay_Medium') OR HasFootprint('Pb-Free_Overlay_Small')) vs (HasFootprint('Pb-Free_Overlay_Medium') OR HasFootprint('Pb-Free_Overlay_Small'))] p1: silktosilkclearance=0
SilkToSilkClearance [All] p2: silktosilkclearance=4
SilkToSolderMaskClearance SilkToComponentPadClearance [(IsPad or IsFill or IsRegion) and InAnycomponent] p1: minsilkscreentomaskgap=5 clearancetoexposedcopper=TRUE
SilkToSolderMaskClearance "Silk to Solder Mask Opening" [All] p2: minsilkscreentomaskgap=4 clearancetoexposedcopper=FALSE
SolderMaskExpansion [All] p1: expansion=1.97 istentingtop=FALSE
Width [All] p1: maxlimit=100 minlimit=6 preferedwidth=10 checkconnectedcopper=TRUE
13 further rules are at their usual default settings.

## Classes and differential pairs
component class PMP41166D_Multi_Level_GaN_Card2: C44 C45 C46 C47 C48 C49 C50 C51 C52 C53 C54 C55 C56 C58 C59 C60 C61 C62 C69 C70 C71 C72 C73 C74 C75 C80 C86 C96 C98 C100 D2 D3 D5 D6 D10 D11 L6 L7 NT1 R1 R2 R3 R4 R8 R9 R11 R12 R13 R14 R26 R29 R30 R31 R32 R33 R42 R46 R48 R53 R60 R63 R74 U1 U2 U3 U10 U11 U12 U13 U16
net class LV: 3V3 5Vp 12Vp HFFET_H2A HFFET_H3A HFFET_L2B HFFET_L3B NetC1_1 NetC2_1 NetC25_1 NetC28_1 NetC69_1 NetC70_1 NetU16_7 PGND SGND_L2B VFLY_SENSE
net class HV: CFLYSENSE ISO_12V_H2A ISO_12V_H3A ISO_12V_L3B NCU1 NCU1' NCU6 NCU9 NCU13 NetC11_1 NetC21_1 NetC24_1 NetC27_1 NetC29_2 NetC30_1 NetC31_1 NetC40_1 NetC41_1 NetC42_1 NetC43_2 NetC44_1 NetC45_1 NetC46_1 NetC47_1 NetC48_2 NetC51_1 NetC68_1 NetC75_1 NetL4_2 NetL5_2 NetL6_2 NetR6_1 NetR9_1 NetR17_2 NetR22_2 NetR27_1 NetR31_2 NetU1_4 NetU1_5 NetU5_13 NetU6_7 NetU8_13 NetU8_15 NetU9_7 NetU12_13 NetU13_7 SGND_H2A SGND_H3A SGND_L3B U4_1 U4_16 U4_17 U4_27 U4_43 U4_47 U4_52 U4_FAULT U4_OC U4_TEMP U7_1 U7_16 U7_17 U7_27 U7_43 U7_47 U7_52 U7_FAULT U7_OC U7_TEMP U10_1 U10_16 U10_17 U10_27 U10_43 U10_47 U10_52 U10_FAULT U10_OC U10_TEMP U11_1 U11_16 Vbulk1
component class PMP41166D_Multi_Level_GaN_Card_Hardware: !PCB Logo1 Logo3 LOGO5 LOGO6
component class Header: J2
component class PMP41166D_Multi_Level_GaN_Card1: BULK C1 C2 C3 C4 C5 C6 C7 C8 C9 C10 C11 C12 C13 C14 C15 C16 C17 C18 C19 C20 C21 C22 C23 C24 C25 C26 C27 C28 C29 C30 C31 C40 C41 C42 C43 C57 C63 C64 C65 C66 C67 C68 D8 D9 J2 L4 L5 PGND R5 R6 R7 R10 R15 R16 R17 R18 R19 R20 R21 R22 R23 R24 R25 R27 R28 R40 SW TH1 TH2 TH3 TH4 TP1 TP2 TP3 U4 U5 U6 U7 U8 U9

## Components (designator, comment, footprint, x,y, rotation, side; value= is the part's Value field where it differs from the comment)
BULK "3621-0-32-15-00-00-08-0" Mill-Max_3621-0-32-xx-00-00-08-0 3982.5,719 r0 top
C1 "CC0402MRX5R6BB105" 0402 6332.5,1912.5 r0 top value=1uF
C2 "CGA2B3X7R1E104K050BB" 0402 6332.5,1832.5 r0 top value=0.1uF
C3 "C1608X5R1E106M080AC" 0603 6355,1990 r90 top value=10uF
C4 "CGA2B3X7R1E104K050BB" 0402 6305,1980 r90 top value=0.1uF
C5 "C3225X7T2J104K160AC" 1210 3562.5,1797.5 r180 bottom value=0.1uF
C6 "C3225X7T2J104K160AC" 1210 3562.5,1673.5 r180 bottom value=0.1uF
C7 "C3225X7T2J104K160AC" 1210 3562.5,1549.5 r180 bottom value=0.1uF
C8 "C3225X7T2J104K160AC" 1210 3562.5,1425.5 r180 bottom value=0.1uF
C9 "C3225X7T2J104K160AC" 1210 3562.5,1301.5 r180 bottom value=0.1uF
C10 "C3225X7T2J104K160AC" 1210 3562.5,1177.5 r180 bottom value=0.1uF
C11 "GRM188R61E106MA73D" 0603 3877.5,1915 r90 top value=10uF
C12 "CKG57NX7T2W225M500JH" CKG57N 4337.5,1067.5 r0 bottom value=2.2uF
C13 "CKG57NX7T2W225M500JH" CKG57N 4337.5,1280 r0 bottom value=2.2uF
C14 "CKG57NX7T2W225M500JH" CKG57N 4337.5,1492.5 r0 bottom value=2.2uF
C15 "CKG57NX7T2W225M500JH" CKG57N 4337.5,1705 r0 bottom value=2.2uF
C16 "CKG57NX7T2W225M500JH" CKG57N 4730,1137.5 r0 bottom value=2.2uF
C17 "CKG57NX7T2W225M500JH" CKG57N 4730,1777.5 r0 bottom value=2.2uF
C18 "CKG57NX7T2W225M500JH" CKG57N 4730,1352.5 r0 bottom value=2.2uF
C19 "CKG57NX7T2W225M500JH" CKG57N 4730,1562.5 r0 bottom value=2.2uF
C20 "GRM188R70J104KA01D" 0603 3710,2377.5 r90 top value=0.1uF
C21 "GCM155R71C224KE02D" 0402 3645,1902.5 r90 top value=0.22uF
C22 "C1608X5R1E106M080AC" 0603 5747.5,2025 r90 top value=10uF
C23 "CGA2B3X7R1E104K050BB" 0402 5797.5,2012.5 r90 top value=0.1uF
C24 "GRM155R71H471KA01D" 0402 5770,1865 r180 top value=470pF
C25 "CC0402MRX5R6BB105" 0402 6332.5,1560 r0 top value=1uF
C26 "C1005C0G1H680J050BA" 0402 3592.5,2457.5 r90 top value=68pF
C27 "CGA2B2C0G1H101J050BA" 0402 3729.17,1902.5 r90 top value=100pF
C28 "CGA2B3X7R1E104K050BB" 0402 6332.5,1480 r0 top value=0.1uF
C29 "GRM155R61E225KE11D" "FP-GRM155R61E225KE11D_0402 (1005 metric)-MFG" 3932.5,1895 r270 top value=2.2µF
C30 "GRM188R61E106MA73D" 0603 4415,1915 r90 top value=10uF
C31 "GRM1555C1H220JA01D" 0402 3812.5,1902.5 r90 top value=22pF
C40 "GCM155R71C224KE02D" 0402 4177.5,1902.5 r90 top value=0.22uF
C41 "GRM1555C1H220JA01D" 0402 4350,1902.5 r90 top value=22pF
C42 "CGA2B2C0G1H101J050BA" 0402 4263.75,1902.5 r90 top value=100pF
C43 "GRM155R61E225KE11D" "FP-GRM155R61E225KE11D_0402 (1005 metric)-MFG" 4475,1892.5 r270 top value=2.2µF
C44 "GRM188R61E106MA73D" 0603 4947.5,1912.5 r90 top value=10uF
C45 "GCM155R71C224KE02D" 0402 4710,1902.5 r90 top value=0.22uF
C46 "GRM1555C1H220JA01D" 0402 4882.5,1902.5 r90 top value=22pF
C47 "CGA2B2C0G1H101J050BA" 0402 4796.25,1902.5 r90 top value=100pF
C48 "GRM155R61E225KE11D" "FP-GRM155R61E225KE11D_0402 (1005 metric)-MFG" 4997.5,1902.5 r270 top value=2.2µF
C49 "C1005X7R1H104K050BB" 0402 5320,2240 r270 bottom value=0.1uF
C50 "GRM1555C1H331FA01J" 0402 6105,1172.5 r180 bottom value=330pF
C51 "CGA2B3X7R1E104K050BB" 0402 5532.5,2310 r270 bottom value=0.1uF
C52 "CGA2B3X7R1E104K050BB" 0402 6035,2305 r180 bottom value=0.1uF
C53 "GRM155R61E105MA12D" 0402 6212.5,1080 r270 bottom value=1uF
C54 "GRM155R61E105MA12D" 0402 5492.5,2310 r270 bottom value=1uF
C55 "GRM155R61E105MA12D" 0402 6035,2262.5 r180 bottom value=1uF
C56 "GRM155R71E222KA01D" 0402 5510,2430 r90 bottom value=2200pF
C57 "GRM188R70J104KA01D" 0603 4310,2377.5 r90 top value=0.1uF
C58 "GRM188R61E106MA73D" 0603 5477.5,1915 r90 top value=10uF
C59 "GCM155R71C224KE02D" 0402 5245,1902.5 r90 top value=0.22uF
C60 "GRM1555C1H220JA01D" 0402 5417.5,1902.5 r90 top value=22pF
C61 "CGA2B2C0G1H101J050BA" 0402 5331.25,1902.5 r90 top value=100pF
C62 "GRM155R61E225KE11D" "FP-GRM155R61E225KE11D_0402 (1005 metric)-MFG" 5532.5,1900 r270 top value=2.2µF
C63 "C1005C0G1H680J050BA" 0402 4190,2465 r90 top value=68pF
C64 "C1608X5R1E106M080AC" 0603 6352.5,1635 r90 top value=10uF
C65 "CGA2B3X7R1E104K050BB" 0402 6305,1622.5 r90 top value=0.1uF
C66 "C1608X5R1E106M080AC" 0603 5747.5,1667.5 r90 top value=10uF
C67 "CGA2B3X7R1E104K050BB" 0402 5797.5,1655 r90 top value=0.1uF
C68 "GRM155R71H471KA01D" 0402 5770,1507.5 r180 top value=470pF
C69 "CC0402MRX5R6BB105" 0402 6332.5,1230 r0 top value=1uF
C70 "CGA2B3X7R1E104K050BB" 0402 6332.5,1150 r0 top value=0.1uF
C71 "C1608X5R1E106M080AC" 0603 6352.5,1305 r90 top value=10uF
C72 "CGA2B3X7R1E104K050BB" 0402 6305,1292.5 r90 top value=0.1uF
C73 "C1608X5R1E106M080AC" 0603 5740,1335 r90 top value=10uF
C74 "CGA2B3X7R1E104K050BB" 0402 5797.5,1322.5 r90 top value=0.1uF
C75 "GRM155R71H471KA01D" 0402 5770,1182.5 r180 top value=470pF
C80 "GRM188R70J104KA01D" 0603 4850,2375 r90 top value=0.1uF
C86 "C1005C0G1H680J050BA" 0402 4742.5,2465 r90 top value=68pF
C96 "GRM188R70J104KA01D" 0603 5385,2372.5 r90 top value=0.1uF
C98 "C1005C0G1H680J050BA" 0402 5282.87,2465.52 r90 top value=68pF
C100 "GRM1555C1H331FA01J" 0402 5990,1102.5 r270 bottom value=330pF
D2 "ZMY150" DO-213AB 3780,1032.5 r0 bottom value=150V
D3 "ZMY150" DO-213AB 4032.5,1032.5 r0 bottom value=150V
D5 "ZMY150" DO-213AB 5182.5,1032.5 r0 bottom value=150V
D6 "ZMY150" DO-213AB 5422.5,1032.5 r0 bottom value=150V
D8 "BZT52C16-7-F" SOD-123 3742.5,2077.5 r90 top value=16V
D9 "BZT52C16-7-F" SOD-123 4300,2077.5 r90 top value=16V
D10 "BZT52C16-7-F" SOD-123 4847.5,2077.5 r90 top value=16V
D11 "BZT52C16-7-F" SOD-123 5387.5,2077.5 r90 top value=16V
J2 "TSW-106-08-G-D-RA" AB12-DEST 6032.5,925 r0 top
L4 "MPIA2510V2-4R7-R" FP-MPIA2510V2-4R7-R_1008-MFG 3920,2042.5 r270 top value=4.7uH
L5 "MPIA2510V2-4R7-R" FP-MPIA2510V2-4R7-R_1008-MFG 4470,2042.5 r270 top value=4.7uH
L6 "MPIA2510V2-4R7-R" FP-MPIA2510V2-4R7-R_1008-MFG 5015,2040 r270 top value=4.7uH
L7 "MPIA2510V2-4R7-R" FP-MPIA2510V2-4R7-R_1008-MFG 5555,2042.5 r270 top value=4.7uH
Logo1 "WEEE logo" WEEE_Minimum 3600,2460 r180 bottom
Logo3 "FCC disclaimer" FCC_disclaimer 2417.5,957.5 r90 bottom
LOGO5 "CAUTION HOT SURFACE" IEC_HotSurface_Small 5472.5,1957.5 r180 bottom
LOGO6 "DANGER HIGH VOLTAGE" IEC_HighVoltage_Small 5732.5,1957.5 r180 bottom
NT1 "Net-Tie" Net-Tie_50milWide_30milLong 5675,1065 r180 top net-tie
PGND "3621-0-32-15-00-00-08-0" Mill-Max_3621-0-32-xx-00-00-08-0 5182.5,719 r0 top
R1 "CRCW04023K30JNED" 0402 6105,1212.5 r0 bottom value=3.3k
R2 "CRCW04023K30JNED" 0402 6112.5,2452.5 r0 bottom value=3.3k
R3 "CRCW04023K30JNED" 0402 6112.5,2402.5 r0 bottom value=3.3k
R4 "CRCW04023K30JNED" 0402 5945,1102.5 r90 bottom value=3.3k
R5 "MCR03EZPJ000" 0603 4365,2042.5 r270 top value=0
R6 "CRCW0402300RJNED" 0402 4306.88,1902.5 r270 top value=300
R7 "MCR01MZPF6982" 0402 3687.5,1902.5 r270 top value=69.8k
R8 "MCR03EZPJ000" 0603 4912.5,2045 r270 top value=0
R9 "CRCW0402300RJNED" 0402 4839.38,1902.5 r270 top value=300
R10 "MCR01MZPF6982" 0402 4220.62,1902.5 r270 top value=69.8k
R11 "MCR03EZPJ000" 0603 5452.5,2042.5 r270 top value=0
R12 "CRCW0402300RJNED" 0402 5374.38,1902.5 r270 top value=300
R13 "MCR01MZPF6982" 0402 4753.12,1902.5 r270 top value=69.8k
R14 "MCR01MZPF6982" 0402 5288.12,1902.5 r270 top value=69.8k
R15 "RT0402BRD0710KL" 0402 6332.5,1872.5 r0 top value=10.0k
R16 "CRCW04025K11FKED" 0402 6332.5,1792.5 r0 top value=5.11k
R17 "RC0402FR-07180KL" 0402 5770,1825 r0 top value=180k
R18 "CRCW040238K3FKED" 0402 5770,1945 r0 top value=38.3k
R19 "RT0402BRD0710KL" 0402 5770,1905 r0 top value=10.0k
R20 "RT0402BRD0710KL" 0402 6332.5,1520 r0 top value=10.0k
R21 "CRCW04025K11FKED" 0402 6332.5,1440 r0 top value=5.11k
R22 "RC0402FR-07180KL" 0402 5770,1467.5 r0 top value=180k
R23 "CRCW040238K3FKED" 0402 5770,1587.5 r0 top value=38.3k
R24 "RT0402BRD0710KL" 0402 5770,1547.5 r0 top value=10.0k
R25 "MCR03EZPJ000" 0603 3807.5,2042.5 r270 top value=0
R26 "RT0402BRD0710KL" 0402 6332.5,1190 r0 top value=10.0k
R27 "CRCW0402300RJNED" 0402 3770.83,1902.5 r270 top value=300
R28 "CRCW040249R9FKED" 0402 3640,2455 r270 top value=49.9
R29 "CRCW04025K11FKED" 0402 6332.5,1110 r0 top value=5.11k
R30 "PHP01206E10R0BST5" 1206 3565,1010 r180 bottom value=10.0
R31 "RC0402FR-07180KL" 0402 5770,1142.5 r0 top value=180k
R32 "CRCW040238K3FKED" 0402 5770,1262.5 r0 top value=38.3k
R33 "RT0402BRD0710KL" 0402 5770,1222.5 r0 top value=10.0k
R40 "CRCW040249R9FKED" 0402 4235,2465 r270 top value=49.9
R42 "RC1206FR-07348KL" 1206 4460,2012.5 r180 bottom value=348k
R46 "RC1206FR-07348KL" 1206 4652.5,2012.5 r180 bottom value=348k
R48 "RC1206FR-07348KL" 1206 4837.5,2030 r180 bottom value=348k
R53 "CRCW04027K50FKED" 0402 5455,2430 r270 bottom value=7.50k
R60 "CRCW040249R9FKED" 0402 4782.5,2465 r270 top value=49.9
R63 "PHP01206E10R0BST5" 1206 4975,1012.5 r180 bottom value=10.0
R74 "CRCW040249R9FKED" 0402 5330,2465 r270 top value=49.9
SW "3621-0-32-15-00-00-08-0" Mill-Max_3621-0-32-xx-00-00-08-0 4682.5,719 r0 top
TH1 "" TP_H045P075 3412.5,1912.5 r90 top
TH2 "" TP_H045P075 3787.5,1187.5 r90 top
TH3 "" TP_H045P075 5137.5,1187.5 r90 top
TH4 "" TP_H045P075 5137.5,1912.5 r90 top
TP1 "3621-0-32-15-00-00-08-0" Mill-Max_3621-0-32-xx-00-00-08-0 4182.5,719 r0 top
TP2 "3621-0-32-15-00-00-08-0" Mill-Max_3621-0-32-xx-00-00-08-0 4482.5,719 r0 top
TP3 "3621-0-32-15-00-00-08-0" Mill-Max_3621-0-32-xx-00-00-08-0 4982.5,719 r0 top
U1 "TLV70450DBVR" DBV0005A_N 5412.6,2266.63 r270 bottom
U2 "AMC0211DDWV" DWV0008A-MFG 5797.5,2427.5 r0 bottom
U3 "TLV9061IDBVR" DBV0005A_N 6100,1090 r0 bottom
U4 "LMG3522R030-Q1" RQS0052C-C01-MFG 3736.14,1575 r0 top
U5 "UCC35131QDHARQ1" DHA0016A-MFG 6051.4,1967.8 r180 top
U6 "ISO7710FDR" D0008B-MFG 3567.5,2237.5 r270 top
U7 "LMG3522R030-Q1" RQS0052C-C01-MFG 4270.76,1575 r0 top
U8 "UCC35131QDHARQ1" DHA0016A-MFG 6051.1,1609.7 r180 top
U9 "ISO7710FDR" D0008B-MFG 4167.5,2237.5 r270 top
U10 "LMG3522R030-Q1" RQS0052C-C01-MFG 4805.38,1575 r0 top
U11 "LMG3522R030-Q1" RQS0052C-C01-MFG 5340,1575 r0 top
U12 "UCC35131QDHARQ1" DHA0016A-MFG 6051.1,1277.2 r180 top
U13 "ISO7710FDR" D0008B-MFG 4717.5,2237.5 r270 top
U16 "ISO7710FDR" D0008B-MFG 5257.5,2237.5 r270 top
